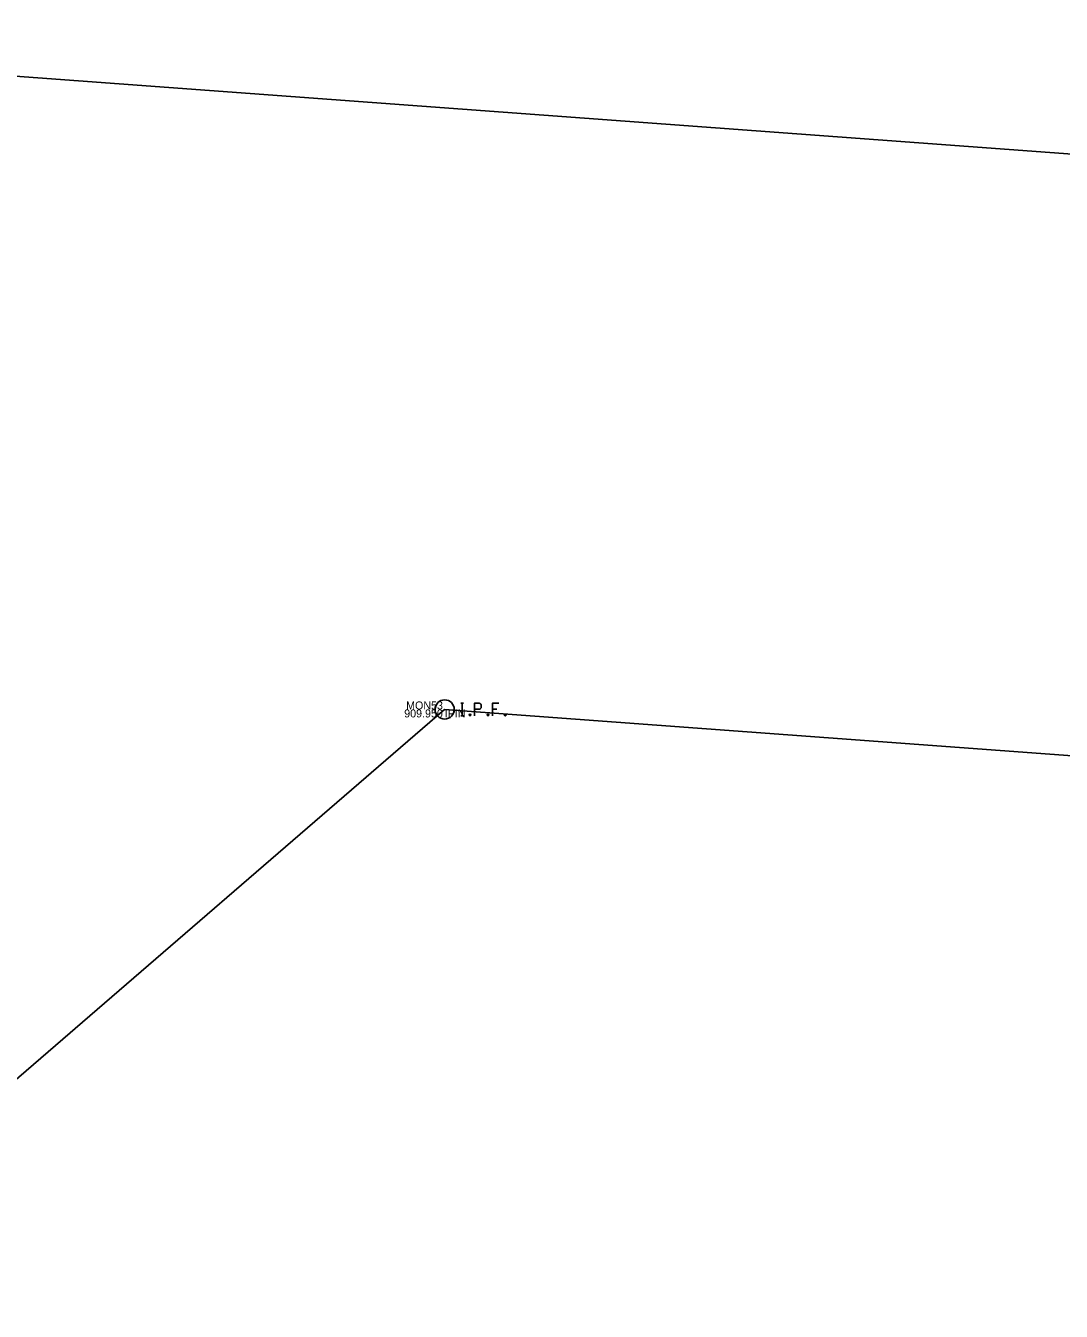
# Model space of a CAD drawing. Extents: x 1981066 to 1984208, y 708139 to 709503.
# Drawn here: x 1982586.1 to 1982715.5, y 708672.4 to 708833.1 of the extents above; entities that cross this region are included whole.
import ezdxf

# ---------------------------------------------------------------- set-up
doc = ezdxf.new("R2010")
doc.units = 0
for name, color, linetype in [('DR_X_Ditch', 7, 'Continuous'), ('DR_X_Elev_Flow', 7, 'Continuous'), ('LT_X_Poles', 7, 'Continuous'), ('SV_X_Shot_Marker', 7, 'Continuous'), ('SV_X_Toe_of_Slope', 7, 'Continuous'), ('UT_X_Misc_Cells', 7, 'Continuous')]:
    doc.layers.add(name, color=color, linetype=linetype)

msp = doc.modelspace()

# ---------------------------------------------------------------- linework, layer by layer
at = {"layer": 'DR_X_Ditch'}
msp.add_line((1982499.31, 708833.12), (1983707.34, 708743.91), dxfattribs=at)
at = {"layer": 'SV_X_Shot_Marker'}
for points in [[(1982640.46, 708748.46), (1982640.81, 708748.46)], [(1982640.64, 708746.86), (1982640.64, 708748.46)], [(1982641.6, 708747.07), (1982641.65, 708747.07), (1982641.68, 708747.05), (1982641.72, 708747), (1982641.72, 708746.93), (1982641.68, 708746.88), (1982641.65, 708746.86), (1982641.6, 708746.86), (1982641.56, 708746.88), (1982641.53, 708746.93), (1982641.53, 708747), (1982641.56, 708747.05), (1982641.6, 708747.07)], [(1982642.2, 708746.86), (1982642.2, 708748.46), (1982642.73, 708748.46), (1982642.79, 708748.44), (1982642.86, 708748.42), (1982642.9, 708748.39), (1982642.93, 708748.37), (1982642.97, 708748.31), (1982643.01, 708748.24), (1982643.03, 708748.14), (1982643.03, 708747.99), (1982643.02, 708747.94), (1982643, 708747.86), (1982642.95, 708747.78), (1982642.91, 708747.74), (1982642.87, 708747.71), (1982642.82, 708747.69), (1982642.73, 708747.68), (1982642.2, 708747.68)], [(1982643.84, 708747.07), (1982643.9, 708747.07), (1982643.93, 708747.05), (1982643.97, 708747), (1982643.97, 708746.93), (1982643.93, 708746.88), (1982643.9, 708746.86), (1982643.84, 708746.86), (1982643.81, 708746.88), (1982643.78, 708746.93), (1982643.78, 708747), (1982643.81, 708747.05), (1982643.84, 708747.07)], [(1982645.21, 708748.46), (1982644.45, 708748.46), (1982644.45, 708746.86)], [(1982644.45, 708747.68), (1982644.99, 708747.68)], [(1982645.99, 708747.07), (1982646.05, 708747.07), (1982646.08, 708747.05), (1982646.12, 708747), (1982646.12, 708746.93), (1982646.08, 708746.88), (1982646.05, 708746.86), (1982645.99, 708746.86), (1982645.96, 708746.88), (1982645.93, 708746.93), (1982645.93, 708747), (1982645.96, 708747.05), (1982645.99, 708747.07)], [(1982640.46, 708746.86), (1982640.81, 708746.86)]]:
    msp.add_lwpolyline(points, dxfattribs=at)
msp.add_circle((1982638.45, 708747.66), 1.2, dxfattribs=at)
at = {"layer": 'SV_X_Toe_of_Slope'}
for p, q in [((1982574.2, 708692.21), (1982638.45, 708747.66)), ((1982638.45, 708747.66), (1983659.59, 708672.43))]:
    msp.add_line(p, q, dxfattribs=at)

# ---------------------------------------------------------------- texts
at = {"layer": 'DR_X_Elev_Flow'}
msp.add_text('909.950', height=1, dxfattribs=at).set_placement((1982633.39, 708746.66))
at = {"layer": 'LT_X_Poles'}
msp.add_text('IPIN', height=1, dxfattribs=at).set_placement((1982638.45, 708746.66))
at = {"layer": 'UT_X_Misc_Cells'}
msp.add_text('MON53', height=1, dxfattribs=at).set_placement((1982633.63, 708747.66))

doc.saveas('drawing.dxf')
